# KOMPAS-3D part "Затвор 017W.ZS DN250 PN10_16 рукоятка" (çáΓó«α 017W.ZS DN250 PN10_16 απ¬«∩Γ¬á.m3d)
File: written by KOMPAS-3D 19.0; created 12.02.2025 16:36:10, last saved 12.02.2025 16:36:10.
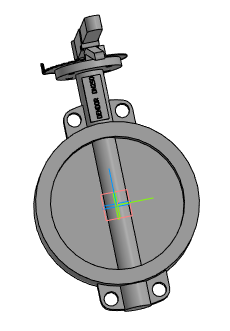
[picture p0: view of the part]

Document properties: Автор: Евгений; Полное имя файла: Затвор 017W.ZS DN250 PN10_16 рукоятка.a3d

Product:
- Part/product: Затвор 017W.ZS DN250 PN10_16 рукоятка
    Масса: 30.8916

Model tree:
1. Операция без истории:1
